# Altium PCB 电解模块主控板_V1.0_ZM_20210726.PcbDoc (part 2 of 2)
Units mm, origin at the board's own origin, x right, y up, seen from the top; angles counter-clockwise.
Board outline 150.25 x 100.26 mm, 2 copper layers (Top Layer, Bottom Layer); 209 components, 149 nets, 716 pads, 1259 vias.
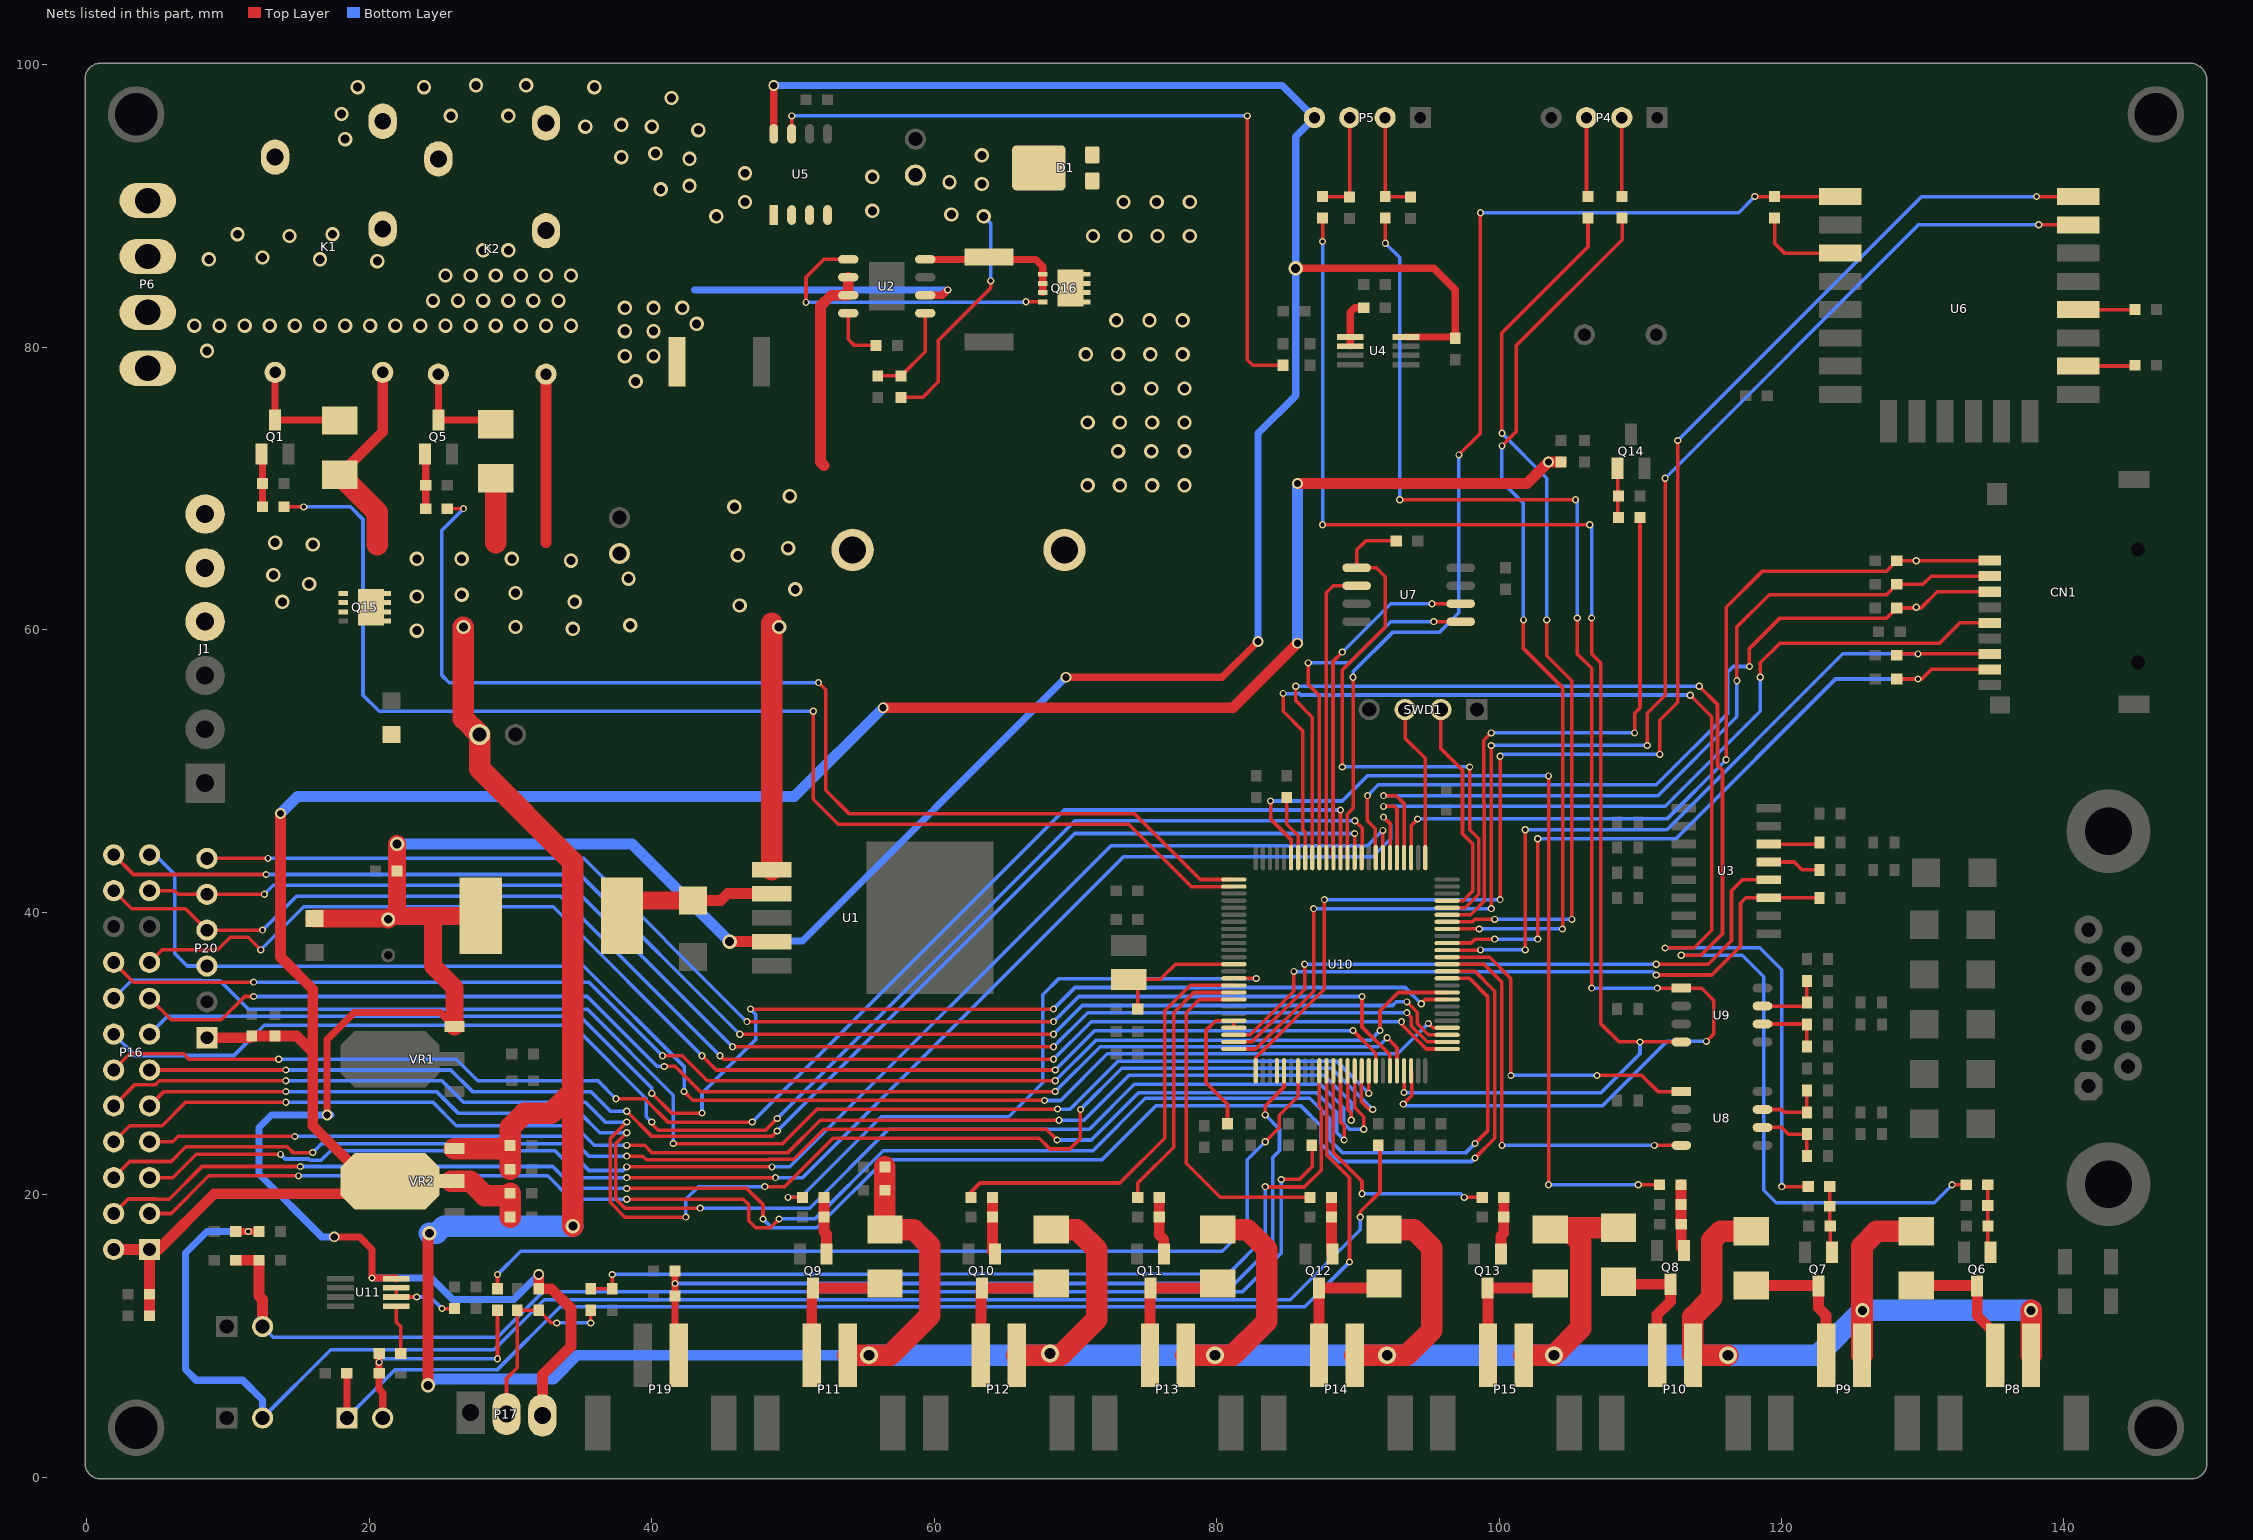
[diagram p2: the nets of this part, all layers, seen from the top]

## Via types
v1: diameter 1.016, hole 0.635, Top Layer to Bottom Layer, tented both sides, 1001 vias
v2: diameter 0.508, hole 0.305, Top Layer to Bottom Layer, tented both sides, 238 vias
v3: diameter 0.762, hole 0.508, Top Layer to Bottom Layer, tented both sides, 14 vias
v4: diameter 1.27, hole 0.762, Top Layer to Bottom Layer, tented both sides, 6 vias

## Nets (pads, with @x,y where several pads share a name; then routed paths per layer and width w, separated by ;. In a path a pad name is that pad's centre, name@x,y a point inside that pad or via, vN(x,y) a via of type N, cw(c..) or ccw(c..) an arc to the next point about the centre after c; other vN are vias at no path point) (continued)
NetC46_2: C46.2 P19.1 R48.1 U10.30 | length 63
  Top Layer w0.254: v2(83.439,25.654) 83.439,26.289 84.773,27.623 U10.30@84.773,28.772
  Top Layer w0.508: R48.1@41.656,14.605 v2(41.656,13.716) C46.2@41.656,12.827 41.656,10.16 41.91,9.906 P19.1@41.91,8.636
  Bottom Layer w0.254: v2(41.656,13.716) 81.28,13.716 83.972,16.408 83.972,22.631 84.455,23.114 84.455,24.638 v2(83.439,25.654)
NetC50_1: C50.1 U10.13 Y1.1 | length 10.2
  Top Layer w0.254: C50.1@74.422,33.147 74.422,34.614 Y1.1@73.787,35.249 76.016,35.249 77.089,36.322 U10.13@81.223,36.322
NetCN1_1: CN1.1 R63.2 U10.78 | length 57.3
  Top Layer w0.254: U10.78@93.773,43.872 93.773,46.148 v2(94.234,46.609) ; v2(116.078,50.8) 116.078,61.595 118.618,64.135 127.406,64.135 R63.2@128.168,64.897 v2(129.54,64.897) CN1.1@134.747,64.897
  Bottom Layer w0.254: v2(94.234,46.609) 111.887,46.609 v2(116.078,50.8)
NetCN1_2: CN1.2 R64.2 U10.79 | length 58.6
  Top Layer w0.254: v2(91.821,48.26) 92.71,48.26 93.273,47.697 U10.79@93.273,43.872 ; v2(116.84,56.388) 116.84,60.198 119.126,62.484 127.432,62.484 R64.2@128.168,63.221 130.023,63.221 130.599,63.797 CN1.2@134.747,63.797
  Bottom Layer w0.254: v2(91.821,48.26) 111.252,48.26 116.84,53.848 v2(116.84,56.388)
NetCN1_3: CN1.3 R65.2 U10.83 | length 57.1
  Top Layer w0.254: v2(90.678,48.26) 90.678,46.482 91.24,45.92 91.24,43.905 U10.83@91.273,43.872 ; v2(117.729,57.404) 117.729,58.674 119.888,60.833 127.457,60.833 R65.2@128.168,61.544 129.87,61.544 131.023,62.697 CN1.3@134.747,62.697
  Bottom Layer w0.254: v2(90.678,48.26) 91.44,49.022 111.125,49.022 116.205,54.102 116.205,57.023 116.586,57.404 v2(117.729,57.404)
  other v2: 129.54,61.595
NetCN1_5: CN1.5 U10.80 | length 54.8
  Top Layer w0.254: v2(91.821,47.498) 92.583,47.498 92.773,47.308 U10.80@92.773,43.872 ; v2(118.491,56.642) 118.491,57.658 119.888,59.055 131.191,59.055 132.633,60.497 CN1.5@134.747,60.497
  Bottom Layer w0.254: v2(91.821,47.498) 111.76,47.498 118.491,54.229 v2(118.491,56.642)
NetCN1_7: CN1.7 R66.2 U10.65 | length 53.7
  Top Layer w0.254: U10.65@96.323,37.322 98.695,37.322 v2(98.679,37.338) ; v2(101.854,37.338) v2(101.854,45.847) ; R66.2@128.168,58.191 128.274,58.297 v2(129.667,58.297) CN1.7@134.747,58.297
  Bottom Layer w0.254: v2(98.679,37.338) v2(101.854,37.338) ; v2(101.854,45.847) 111.887,45.847 124.337,58.297 v2(129.667,58.297)
NetCN1_8: CN1.8 R67.2 U10.66 | length 52.1
  Top Layer w0.254: U10.66@96.323,37.822 98.02,37.822 98.298,38.1 v2(99.695,38.1) ; v2(102.743,38.1) v2(102.743,45.212) ; R67.2@128.168,56.515 v2(129.667,56.515) 129.921,56.515 130.603,57.197 CN1.8@134.747,57.197
  Bottom Layer w0.254: v2(99.695,38.1) v2(102.743,38.1) ; v2(102.743,45.212) 112.522,45.212 123.825,56.515 v2(129.667,56.515)
NetD1_1: D1.1 L2.2 Q16.2
  other v1: 70.866,70.231 73.152,70.231 75.438,70.231 77.724,70.231 73.025,72.644 75.374,72.644 77.724,72.644 70.866,74.676 73.152,74.676 75.438,74.676 77.724,74.676 73.025,77.089 75.374,77.089 77.724,77.089 70.739,79.502 73.025,79.502 75.311,79.502 77.597,79.502 72.898,81.915 75.248,81.915 77.597,81.915 71.247,87.884 73.533,87.884 75.819,87.884 78.105,87.884 73.406,90.297 75.755,90.297 78.105,90.297
NetD3_2: D3.2 L1.1 U1.2 | length 11.3
  Top Layer w0.762: L1.1@37.893,39.751 L1.1@38.972,40.83 ; D3.2@42.926,40.83 44.894,40.83 45.388,41.324 U1.2@48.514,41.324
  Top Layer w1.27: L1.1@38.972,40.83 D3.2@42.926,40.83
NetD4_1: D4.1 K1.4 Q1.3 | length 8
  Top Layer w0.508: K1.4@13.335,78.232 Q1.3@13.335,74.86 17.86,74.86 D4.1@17.907,74.813
NetD5_1: D5.1 K2.4 Q5.3 | length 7.4
  Top Layer w0.508: K2.4@24.892,78.105 Q5.3@24.892,74.86 28.655,74.86 D5.1@28.956,74.559
NetD6_1: D6.1 P8.2 Q6.3 | length 9.8
  Top Layer w0.762: D6.1@129.54,13.579 133.811,13.579 Q6.3@133.858,13.532 133.858,11.43 135.128,10.16 P8.2@135.128,8.636
NetD7_1: D7.1 P9.2 Q7.3 | length 9.9
  Top Layer w0.762: D7.1@117.856,13.579 122.571,13.579 Q7.3@122.618,13.532 122.618,12.002 123.158,11.462 P9.2@123.158,8.636
NetD8_1: D8.1 P10.2 Q8.3 | length 9.2
  Top Layer w0.762: D8.1@108.458,13.833 108.632,13.659 Q8.3@112.141,13.659 112.141,12.446 111.188,11.493 P10.2@111.188,8.636
NetD9_1: D9.1 P11.2 Q9.3 | length 10
  Top Layer w0.762: P11.2@51.34,8.636 51.34,13.31 Q9.3@51.435,13.405 56.214,13.405 D9.1@56.515,13.706
NetD10_1: D10.1 P12.2 Q10.3 | length 9.8
  Top Layer w0.762: P12.2@63.309,8.636 63.309,13.341 Q10.3@63.373,13.405 67.993,13.405 D10.1@68.294,13.706
NetD11_1: D11.1 P13.2 Q11.3 | length 9.7
  Top Layer w0.762: P13.2@75.279,8.636 75.279,13.373 Q11.3@75.311,13.405 79.772,13.405 D11.1@80.073,13.706
NetD12_1: D12.1 P14.2 Q12.3 | length 9.5
  Top Layer w0.762: P14.2@87.249,8.636 Q12.3@87.249,13.405 91.552,13.405 D12.1@91.853,13.706
NetD13_1: D13.1 P15.2 Q13.3 | length 9.4
  Top Layer w0.762: P15.2@99.219,8.636 99.219,13.373 Q13.3@99.187,13.405 103.331,13.405 D13.1@103.632,13.706
NetJ1_4: J1.4 J1.5 J1.6 Q15.3
  other v1: 13.843,61.976 15.748,63.246 13.208,63.881 16.002,66.04 13.335,66.167
NetK1_1: K1.1 P6.3 P6.4
  other v1: 20.574,86.106 8.636,86.233 16.51,86.233 12.446,86.36 14.351,87.884 10.668,88.011 17.399,88.011
NetK2_1: K2.1 P6.1 P6.2
  other v1: 8.509,79.756 7.62,81.534 9.398,81.534 11.176,81.534 12.954,81.534 14.732,81.534 16.51,81.534 18.288,81.534 20.066,81.534 21.844,81.534 23.622,81.534 25.4,81.534 27.178,81.534 28.956,81.534 30.734,81.534 32.512,81.534 34.29,81.534 24.511,83.312 26.289,83.312 28.067,83.312 29.845,83.312 31.623,83.312 33.401,83.312 25.4,85.09 27.178,85.09 28.956,85.09 30.734,85.09 32.512,85.09 34.29,85.09 28.067,86.868 29.845,86.868
NetL3_2: L3.2 U10.21 U10.22 | length 10
  Top Layer w0.254: L3.2@80.772,25.019 80.772,26.416 79.248,27.94 79.248,31.623 79.947,32.322 U10.21@81.223,32.322 U10.22@81.223,31.822
NetP1_1: P1.1 TVS5.2 U10.36 | length 93
  Top Layer w0.254: U10.36@87.773,28.772 87.808,28.737 87.808,22.809 89.408,21.209 v2(89.408,15.24)
  Top Layer w0.508: P1.1@18.415,4.191 TVS5.2@18.415,7.366
  Bottom Layer w0.254: P1.1@18.415,4.191 21.844,7.62 29.083,7.62 33.528,12.065 86.233,12.065 v2(89.408,15.24)
NetP1_2: P1.2 R14.2 R16.1 TVS6.2 | length 16.6
  Top Layer w0.254: v2(29.083,8.382) R14.2@29.083,11.811
  Top Layer w0.508: R16.1@20.701,8.763 v2(20.701,8.128) TVS6.2@20.701,7.366 20.701,6.223 20.955,5.969 P1.2@20.955,4.191
  Bottom Layer w0.254: v2(20.701,8.128) 20.955,8.382 v2(29.083,8.382)
NetP2_2: P2.2 R5.2 R7.1 TVS1.2 | length 112.5
  Top Layer w0.254: 11.684,17.399 R5.2@12.192,17.399 ; v2(90.17,18.415) 90.17,18.796 91.567,20.193 91.567,23.368 R7.1@91.44,23.495
  Top Layer w0.508: TVS1.2@10.541,17.399 v2(11.43,17.399) 11.684,17.399
  Bottom Layer w0.254: P2.2@12.446,4.191 17.272,9.017 28.829,9.017 32.385,12.573 85.217,12.573 90.17,17.526 v2(90.17,18.415)
  Bottom Layer w0.508: v2(11.43,17.399) 8.509,17.399 6.985,15.875 6.985,7.62 7.747,6.858 11.049,6.858 12.446,5.461 P2.2@12.446,4.191
NetP3_2: P3.2 R6.2 R8.1 TVS2.2 | length 90.7
  Top Layer w0.254: v2(84.582,21.082) 85.852,21.082 86.766,21.996 86.766,23.47 R8.1@86.741,23.495
  Top Layer w0.762: TVS2.2@10.541,15.367 R6.2@12.192,15.367 12.192,12.827 12.446,12.573 P3.2@12.446,10.668
  Bottom Layer w0.254: P3.2@12.446,10.668 13.208,9.906 29.083,9.906 32.322,13.144 81.852,13.144 84.582,15.875 v2(84.582,21.082)
NetP4_2: P4.2 R11.1 | length 5.6
  Top Layer w0.254: P4.2@108.692,96.266 108.692,90.698 R11.1@108.712,90.678
NetP4_3: P4.3 R9.1 | length 5.6
  Top Layer w0.254: P4.3@106.192,96.266 106.192,90.785 R9.1@106.299,90.678
NetP5_2: P5.2 R12.1 TVS4.2 | length 7.4
  Top Layer w0.254: P5.2@91.928,96.266 91.928,90.698 R12.1@91.948,90.678 93.701,90.678 TVS4.2@93.726,90.653
NetP5_3: P5.3 R10.1 TVS3.2 | length 7.5
  Top Layer w0.254: R10.1@87.503,90.678 89.383,90.678 TVS3.2@89.408,90.653 89.428,90.673 P5.3@89.428,96.266
NetP16_3: P16.3 U10.61 | length 117.9
  Top Layer w0.254: P16.3@4.445,18.669 5.969,18.669 8.636,21.336 v2(14.986,21.336) ; v2(38.227,19.685) 46.482,19.685 46.863,19.304 46.863,18.161 47.371,17.653 48.387,17.653 v2(49.022,18.288) ; U10.61@96.323,35.322 97.901,35.322 99.187,34.036 99.187,24.511 v2(98.298,23.622)
  Bottom Layer w0.254: v2(14.986,21.336) 32.639,21.336 34.29,19.685 v2(38.227,19.685) ; v2(49.022,18.288) 51.562,18.288 56.388,23.114 71.247,23.114 74.955,26.822 86.589,26.822 88.011,25.4 88.011,23.876 88.9,22.987 97.663,22.987 v2(98.298,23.622)
NetP16_4: P16.4 U10.62 | length 122.6
  Top Layer w0.254: P16.4@1.905,18.669 2.934,19.698 4.871,19.698 4.885,19.685 5.842,19.685 8.153,21.996 v2(15.123,21.996) ; v2(38.227,20.447) 46.736,20.447 47.879,19.304 v2(47.879,18.288) ; U10.62@96.323,35.822 98.29,35.822 99.695,34.417 99.695,24.003 v2(98.298,22.606)
  Bottom Layer w0.254: v2(15.123,21.996) 32.995,21.996 34.544,20.447 v2(38.227,20.447) ; v2(47.879,18.288) 48.514,17.653 51.689,17.653 56.515,22.479 71.882,22.479 75.692,26.289 85.979,26.289 87.376,24.892 87.376,23.622 88.646,22.352 98.044,22.352 v2(98.298,22.606)
NetP16_5: P16.5 U10.81 | length 104.7
  Top Layer w0.254: P16.5@4.445,21.209 6.096,21.209 7.747,22.86 v2(13.716,22.86) ; v2(38.227,21.209) v2(48.768,21.209) ; v2(91.821,46.736) 92.306,46.251 92.306,43.905 U10.81@92.273,43.872
  Bottom Layer w0.254: v2(13.716,22.86) 14.046,22.53 15.705,22.53 15.781,22.454 16.612,22.454 17.272,23.114 33.147,23.114 35.052,21.209 v2(38.227,21.209) ; v2@48.641,21.209 v2(48.768,21.209) 50.673,21.209 73.406,43.942 91.059,43.942 92.329,45.212 92.329,46.228 v2(91.821,46.736)
NetP16_6: P16.6 U10.82 | length 103.8
  Top Layer w0.254: P16.6@1.905,21.209 3.048,22.352 5.969,22.352 7.01,23.393 14.199,23.393 14.605,22.987 v2(16.002,22.987) ; v2(38.227,21.971) v2(48.514,21.971) ; U10.82@91.773,43.872 v2(91.773,45.799)
  Bottom Layer w0.254: v2(16.002,22.987) 16.637,23.622 33.655,23.622 35.56,21.717 37.973,21.717 v2(38.227,21.971) ; v2@48.641,21.971 49.784,21.971 72.517,44.704 90.678,44.704 v2(91.773,45.799)
NetP16_7: P16.7 U10.38 | length 95.2
  Top Layer w0.254: P16.7@4.445,23.749 6.096,23.749 6.477,24.13 v2(14.732,24.13) ; v2(38.227,22.733) 39.37,22.733 39.624,22.479 48.268,22.479 48.293,22.504 50.063,22.504 52.197,24.638 67.945,24.638 v2(68.707,23.876) ; U10.38@88.773,28.772 88.773,25.146 89.027,24.892 v2(89.027,23.876)
  Bottom Layer w0.254: v2(14.732,24.13) 34.163,24.13 35.56,22.733 v2(38.227,22.733) ; v2(68.707,23.876) 71.12,23.876 74.473,27.229 87.071,27.229 88.519,25.781 88.519,24.384 v2(89.027,23.876)
NetP16_8: P16.8 U10.39 | length 98.2
  Top Layer w0.254: P16.8@1.905,23.749 3.048,24.892 5.334,24.892 6.985,26.543 v2(14.097,26.543) ; v2(38.227,23.495) 39.497,23.495 40.005,22.987 49.657,22.987 51.943,25.273 v2(68.834,25.273) ; U10.39@89.273,28.772 89.273,26.043 89.535,25.781 v2(89.535,25.273)
  Bottom Layer w0.254: v2(14.097,26.543) 24.511,26.543 26.162,24.892 34.544,24.892 35.941,23.495 v2(38.227,23.495) ; v2(68.834,25.273) 70.612,25.273 73.787,28.448 87.63,28.448 89.535,26.543 v2(89.535,25.273)
NetP16_9: P16.9 U10.40 | length 103.6
  Top Layer w0.254: P16.9@4.445,26.289 5.461,27.305 v2(14.097,27.305) ; v2(38.227,24.384) 37.465,23.622 37.465,19.693 38.108,19.05 v2(43.434,19.05) ; U10.40@89.773,28.772 89.773,26.178 90.424,25.527 v2(90.424,24.638)
  Bottom Layer w0.254: v2(14.097,27.305) 24.765,27.305 26.289,25.781 34.925,25.781 36.322,24.384 v2(38.227,24.384) ; v2(43.434,19.05) 51.181,19.05 56.769,24.638 70.993,24.638 74.168,27.813 87.351,27.813 89.002,26.162 89.002,25.052 89.416,24.638 v2(90.424,24.638)
NetP16_10: P16.10 U10.41 | length 110.3
  Top Layer w0.254: P16.10@1.905,26.289 3.416,27.8 4.871,27.8 5.139,28.067 v2(14.097,28.067) ; v2(38.227,25.146) 37.059,23.978 37.059,19.456 38.1,18.415 v2(42.418,18.415) ; v2(48.006,20.574) 49.403,20.574 52.832,24.003 67.437,24.003 68.199,23.241 69.596,23.241 70.358,24.003 v2(70.358,26.035) ; U10.41@90.273,28.772 90.24,28.739 90.24,26.6 90.805,26.035 v2(91.059,26.035)
  Bottom Layer w0.254: v2(14.097,28.067) 25.146,28.067 26.67,26.543 35.306,26.543 36.703,25.146 v2(38.227,25.146) ; v2(42.418,18.415) 42.418,19.685 43.307,20.574 v2(48.006,20.574) ; v2(70.358,26.035) 73.279,28.956 88.138,28.956 v2(91.059,26.035)
NetP16_11: P16.11 U10.86 | length 97.8
  Top Layer w0.254: P16.11@4.445,28.829 v2(14.097,28.829) ; v2(38.227,25.908) 39.98,24.155 48.539,24.155 v2(48.895,24.511) ; U10.86@89.773,43.872 v2(89.773,45.577)
  Bottom Layer w0.254: v2(14.097,28.829) 25.781,28.829 27.305,27.305 35.687,27.305 37.084,25.908 v2(38.227,25.908) ; v2(48.895,24.511) 69.961,45.577 v2(89.773,45.577)
NetP16_12: P16.12 U10.88 | length 101.9
  Top Layer w0.254: P16.12@1.905,28.829 3.048,29.972 6.858,29.972 7.239,29.591 v2(13.589,29.591) ; v2(37.465,26.797) 39.497,26.797 41.148,25.146 v2(47.117,25.146) ; U10.88@88.773,43.872 v2(88.773,47.244)
  Bottom Layer w0.254: v2(13.589,29.591) 26.162,29.591 27.686,28.067 36.195,28.067 v2(37.465,26.797) ; v2(47.117,25.146) 69.215,47.244 v2(88.773,47.244)
NetP16_13: P16.13 U10.58 | length 102.4
  Top Layer w0.254: v2(40.005,27.178) 41.402,25.781 v2(43.561,25.781) ; v2(46.99,33.147) v2(68.453,33.147) ; v2(94.488,33.528) 94.782,33.822 U10.58@96.323,33.822
  Bottom Layer w0.254: P16.13@4.445,31.369 5.702,32.626 13.322,32.626 13.335,32.639 34.925,32.639 40.005,27.559 v2(40.005,27.178) ; v2(43.561,25.781) 43.561,27.178 47.371,30.988 47.371,32.766 v2(46.99,33.147) ; v2(68.453,33.147) 69.977,34.671 93.345,34.671 v2(94.488,33.528)
NetP16_14: P16.14 U10.85 | length 105.2
  Top Layer w0.254: v2(40.005,25.146) 40.005,25.019 40.462,24.562 48.057,24.562 v2(48.895,25.4) ; v2(89.789,46.482) 90.306,45.965 90.306,43.905 U10.85@90.273,43.872
  Bottom Layer w0.254: P16.14@1.905,31.369 3.416,29.858 10.427,29.858 12.56,31.991 34.43,31.991 39.624,26.797 39.624,25.527 v2(40.005,25.146) ; v2(48.895,25.4) 69.977,46.482 v2(89.789,46.482)
NetP16_15: P16.15 U10.46 | length 95.9
  Top Layer w0.254: P16.15@4.445,33.909 5.969,32.385 9.525,32.385 11.176,34.036 v2(11.811,34.036) ; v2(40.894,29.083) 41.656,29.083 43.434,27.305 v2(68.58,27.305) ; v2(92.075,31.115) 92.773,30.417 U10.46@92.773,28.772
  Bottom Layer w0.254: v2(11.811,34.036) 35.433,34.036 40.386,29.083 v2(40.894,29.083) ; v2(68.58,27.305) 71.755,30.48 91.44,30.48 v2(92.075,31.115)
NetP16_16: P16.16 U10.42 | length 101.2
  Top Layer w0.254: v2(41.529,23.622) 49.276,23.622 51.721,26.067 v2(68.739,26.067) ; v2(90.773,27.178) U10.42@90.773,28.772
  Bottom Layer w0.254: P16.16@1.905,33.909 3.175,35.179 8.069,35.179 8.083,35.166 9.411,35.166 11.43,33.147 35.433,33.147 41.529,27.051 v2(41.529,23.622) ; v2(68.739,26.067) 69.628,26.067 73.025,29.464 88.487,29.464 v2(90.773,27.178)
NetP16_17: P16.17 U10.43 | length 97
  Top Layer w0.254: P16.17@4.445,36.449 5.334,37.338 9.271,37.338 10.16,38.227 11.43,38.227 v2(12.319,37.338) ; v2(43.561,29.845) 44.577,28.829 v2(68.58,28.829) ; v2(89.662,31.623) 91.273,30.012 U10.43@91.273,28.772
  Bottom Layer w0.254: v2(12.319,37.338) 15.367,40.386 33.02,40.386 v2(43.561,29.845) ; v2(68.58,28.829) 71.374,31.623 v2(89.662,31.623)
NetP16_18: P16.18 U10.59 | length 101.3
  Top Layer w0.254: P16.18@1.905,36.449 3.302,35.052 v2(11.811,35.052) ; v2(40.767,29.845) 42.164,29.845 43.942,28.067 v2(68.58,28.067) ; v2(91.567,31.623) 91.567,33.02 92.869,34.322 U10.59@96.323,34.322
  Bottom Layer w0.254: v2(11.811,35.052) 35.56,35.052 v2(40.767,29.845) ; v2(68.58,28.067) 71.438,30.924 90.868,30.924 v2(91.567,31.623)
NetP16_21: P16.21 P20.5 U10.52 | length 99.2
  Top Layer w0.254: P16.21@4.445,41.529 6.223,41.529 6.477,41.275 P20.5@8.509,41.275 v2(12.573,41.275) ; v2(45.72,30.48) v2(68.453,30.48) ; v2(93.472,32.893) 93.789,32.575 93.789,31.954 94.921,30.822 U10.52@96.323,30.822
  Bottom Layer w0.254: v2(12.573,41.275) 13.208,41.91 34.29,41.91 v2(45.72,30.48) ; v2(68.453,30.48) 70.866,32.893 v2(93.472,32.893)
NetP16_22: P16.22 P20.4 U10.51 | length 103.4
  Top Layer w0.254: P16.22@1.905,41.529 3.175,40.259 6.985,40.259 P20.4@8.509,38.735 v2(12.446,38.735) ; v2(44.831,29.845) 45.085,29.591 v2(68.453,29.591) ; v2(93.091,32.258) 93.091,32.078 94.847,30.322 U10.51@96.323,30.322
  Bottom Layer w0.254: v2(12.446,38.735) 14.859,41.148 33.528,41.148 v2(44.831,29.845) ; v2(68.453,29.591) 71.12,32.258 v2(93.091,32.258)
NetP16_23: P16.23 P20.3 U10.54 | length 105.8
  Top Layer w0.254: v2(42.291,27.305) 42.901,26.695 67.793,26.695 v2(67.818,26.67) ; v2(94.996,32.131) 95.305,31.822 U10.54@96.323,31.822
  Bottom Layer w0.254: P16.23@4.445,44.069 4.826,44.069 6.223,42.672 6.223,37.084 7.112,36.195 P20.3@8.509,36.195 8.509,36.178 35.196,36.178 42.291,29.083 v2(42.291,27.305) ; v2(67.818,26.67) 68.961,26.67 72.263,29.972 92.837,29.972 v2(94.996,32.131)
NetP16_24: P16.24 U10.53 | length 102.1
  Top Layer w0.254: P16.24@1.905,44.069 3.302,42.672 v2(12.7,42.672) ; v2(46.228,31.369) v2(68.453,31.369) ; v2(93.472,33.655) 94.196,32.931 94.196,32.122 94.996,31.322 U10.53@96.323,31.322
  Bottom Layer w0.254: v2(12.7,42.672) 34.925,42.672 v2(46.228,31.369) ; v2(68.453,31.369) 70.485,33.401 92.456,33.401 92.71,33.655 v2(93.472,33.655)
NetP17_2: P17.2 R19.1 R50.2 TVS11.2 | length 14.1
  Top Layer w0.254: P17.2@29.718,4.472 29.718,6.985 30.48,7.747 TVS11.2@30.48,11.811 R50.2@32.004,11.811 32.893,10.922 v2(33.274,10.922) ; v2(35.687,10.922) R19.1@35.687,11.811
  Bottom Layer w0.254: v2(33.274,10.922) v2(35.687,10.922)
NetP20_6: P20.6 U10.45 | length 93.4
  Top Layer w0.254: P20.6@8.509,43.815 v2(12.827,43.815) ; v2(46.736,32.258) v2(68.453,32.258) ; v2(90.297,34.036) 90.297,31.877 92.273,29.901 U10.45@92.273,28.772
  Bottom Layer w0.254: v2(12.827,43.815) 35.179,43.815 v2(46.736,32.258) ; v2(68.453,32.258) 70.231,34.036 v2(90.297,34.036)
NetQ1_1: Q1.1 R20.2 R21.2 | length 3.8
  Top Layer w0.508: Q1.1@12.385,72.46 12.446,72.399 R21.2@12.446,70.358 R20.2@12.446,68.707
NetQ5_1: Q5.1 R27.2 R28.2 | length 3.9
  Top Layer w0.508: Q5.1@23.942,72.46 24.003,72.399 R28.2@24.003,70.231 R27.2@24.003,68.58
NetQ6_1: Q6.1 R31.1 R34.1 TVS8.2 | length 4.9
  Top Layer w0.254: R31.1@134.595,20.701 R34.1@134.595,19.241 134.595,16.145 Q6.1@134.808,15.932
NetQ7_1: Q7.1 R32.1 R35.1 TVS9.2 | length 4.7
  Top Layer w0.254: R32.1@123.419,20.574 R35.1@123.419,19.177 123.419,17.805 TVS9.2@123.444,17.78 123.444,16.056 Q7.1@123.568,15.932
NetQ8_1: Q8.1 R33.1 R36.1 TVS10.2 | length 4.7
  Top Layer w0.762: R33.1@112.878,20.701 R36.1@112.878,19.304 112.878,17.932 TVS10.2@112.903,17.907 112.903,16.247 Q8.1@113.091,16.059
NetQ9_1: Q9.1 R37.1 R42.1 | length 4.1
  Top Layer w0.762: R37.1@52.197,19.812 R42.1@52.197,18.415 52.197,17.399 52.385,17.211 Q9.1@52.385,15.805
NetQ10_1: Q10.1 R38.1 R43.1 | length 4.1
  Top Layer w0.762: R38.1@64.135,19.812 R43.1@64.135,18.415 64.135,15.993 Q10.1@64.323,15.805
NetQ11_1: Q11.1 R39.1 R44.1 | length 4.1
  Top Layer w0.762: R39.1@75.946,19.812 R44.1@75.946,18.415 75.946,17.145 76.261,16.83 Q11.1@76.261,15.805
NetQ12_1: Q12.1 R40.1 R45.1 | length 4
  Top Layer w0.762: R40.1@88.138,19.812 R45.1@88.138,18.415 88.138,15.866 Q12.1@88.199,15.805
NetQ13_1: Q13.1 R41.1 R46.1 | length 4.1
  Top Layer w0.762: Q13.1@100.137,15.805 100.137,17.079 100.33,17.272 R46.1@100.33,18.415 R41.1@100.33,19.812
NetQ14_1: Q14.1 R57.2 R59.1 | length 3.5
  Top Layer w0.254: Q14.1@108.397,71.444 108.397,68.006 R57.2@108.458,67.945
NetQ16_1: Q16.1 U2.1 | length 22.1
  Top Layer w0.254: v2(50.927,83.185) 50.927,84.963 52.197,86.233 U2.1@53.917,86.233 ; v2(66.507,83.226) Q16.1@67.69,83.226
  Bottom Layer w0.254: v2(50.927,83.185) 66.466,83.185 v2(66.507,83.226)
NetQ16_3: Q16.3 R4.1 U2.8 | length 10.4
  Top Layer w0.508: U2.8@59.367,86.233 67.183,86.233 67.69,85.726 Q16.3@67.69,85.176 Q16.3@67.69,84.526 Q16.3@67.69,83.876
NetR2_2: R2.2 R13.1 U2.5 | length 6.8
  Top Layer w0.254: R13.1@56.007,77.978 R2.2@57.658,77.978 59.367,79.687 U2.5@59.367,82.423
NetR3_1: R3.1 U2.4 | length 4
  Top Layer w0.254: U2.4@53.917,82.423 53.917,80.576 54.356,80.137 R3.1@55.88,80.137
NetR9_2: R9.2 U10.69 | length 63.1
  Top Layer w0.254: U10.69@96.323,39.322 98.123,39.322 98.298,39.497 v2(99.695,39.497) ; v2(100.203,73.914) 100.203,81.026 106.299,87.122 R9.2@106.299,89.154 ; v2(103.378,60.706) 103.378,58.166 105.156,56.388 v2(105.156,39.497)
  Bottom Layer w0.254: v2(99.695,39.497) v2(105.156,39.497) ; v2(100.203,73.914) 103.378,70.739 v2(103.378,60.706)
NetR11_2: R11.2 U10.68 | length 63.8
  Top Layer w0.254: U10.68@96.323,38.822 v2(98.592,38.822) ; v2(100.203,73.025) 101.219,74.041 101.219,80.137 108.712,87.63 R11.2@108.712,89.154 ; v2(101.727,60.706) 101.727,58.674 104.521,55.88 104.521,38.862 v2(104.481,38.822)
  Bottom Layer w0.254: v2(98.592,38.822) v2(104.481,38.822) ; v2(100.203,73.025) 100.203,70.485 101.727,68.961 v2(101.727,60.706)
NetR14_1: R14.1 U10.32 | length 68
  Top Layer w0.254: R14.1@29.083,13.335 v2(29.083,14.351) ; v2(83.439,23.749) 84.43,24.74 84.43,25.629 85.773,26.972 U10.32@85.773,28.772
  Bottom Layer w0.254: v2(29.083,14.351) 30.734,16.002 80.391,16.002 82.169,17.78 82.169,22.479 v2(83.439,23.749)
NetR16_2: R16.2 U11.5 | length 3.5
  Top Layer w0.254: U11.5@21.914,12.106 21.914,10.979 22.225,10.668 R16.2@22.225,8.763
NetR18_2: R18.2 U11.6 U11.7 | length 5.1
  Top Layer w0.254: U11.7@21.914,13.406 U11.6@21.914,12.756 v2(23.368,12.756) ; v2(25.146,11.938) R18.2@26.035,11.938
  Bottom Layer w0.254: v2(23.368,12.756) 24.328,12.756 v2(25.146,11.938)
NetR19_2: R19.2 R22.2 U10.35 | length 64.8
  Top Layer w0.254: R19.2@35.687,13.335 R22.2@37.211,13.335 v2(37.211,14.351) ; v2(83.439,20.574) 83.464,20.549 86.208,20.549 87.401,21.742 87.401,26.137 87.273,26.265 U10.35@87.273,28.772
  Bottom Layer w0.254: v2(37.211,14.351) 80.835,14.414 83.439,17.018 v2@83.439,20.447
NetR20_1: R20.1 U10.2 | length 89.3
  Top Layer w0.254: R20.1@13.97,68.707 v2(15.367,68.707) ; v2(51.435,54.229) 51.435,48.006 53.213,46.228 73.787,46.228 78.193,41.822 U10.2@81.223,41.822
  Bottom Layer w0.254: v2(15.367,68.707) 18.669,68.707 19.558,67.818 19.558,55.372 20.701,54.229 v2(51.435,54.229)
NetR27_1: R27.1 U10.1 | length 79.8
  Top Layer w0.254: R27.1@25.527,68.58 v2(26.67,68.58) ; v2(51.816,56.261) 52.324,55.753 52.324,48.641 53.975,46.99 74.168,46.99 78.836,42.322 U10.1@81.223,42.322
  Bottom Layer w0.254: v2(26.67,68.58) 25.146,67.056 25.146,56.769 25.654,56.261 v2(51.816,56.261)
NetR29_2: R29.2 U4.1 U4.2 | length 3.5
  Top Layer w0.508: U4.2@89.465,80.091 U4.1@89.465,80.731 89.465,82.48 89.789,82.804 R29.2@90.424,82.804
NetR30_2: R30.2 U5.7 | length 53.5
  Top Layer w0.254: U5.7@49.911,95.123 v2(49.911,96.393) ; v2(82.169,96.393) 82.169,79.121 82.55,78.74 R30.2@84.709,78.74
  Bottom Layer w0.254: v2(49.911,96.393) v2(82.169,96.393)
NetR31_2: R31.2 U10.92 | length 99.8
  Top Layer w0.254: v2(85.598,56.007) 85.598,54.991 86.773,53.816 U10.92@86.773,43.872 ; v2(112.903,36.957) 114.3,36.957 115.824,38.481 115.824,50.063 115.468,50.419 115.468,54.712 v2(114.173,56.007) ; v2(132.08,20.701) R31.2@133.071,20.701
  Bottom Layer w0.254: v2(85.598,56.007) v2(114.173,56.007) ; v2(112.903,36.957) 117.221,36.957 118.745,35.433 118.745,20.32 119.634,19.431 130.81,19.431 v2(132.08,20.701)
NetR32_2: R32.2 U10.93 | length 88.4
  Top Layer w0.254: v2(84.709,55.499) 84.709,54.229 86.106,52.832 86.106,45.847 86.273,45.68 U10.93@86.273,43.872 ; v2(111.76,37.465) 111.785,37.49 113.817,37.49 115.062,38.735 115.062,53.848 v2(113.538,55.372) ; v2(120.015,20.574) R32.2@121.895,20.574
  Bottom Layer w0.254: v2(84.709,55.499) 84.734,55.474 85.819,55.474 85.844,55.499 85.958,55.385 113.525,55.385 v2(113.538,55.372) ; v2(111.76,37.465) 111.785,37.49 118.466,37.49 120.015,35.941 v2(120.015,20.574)
NetR33_2: R33.2 U10.95 | length 61.8
  Top Layer w0.254: v2(83.82,47.879) 83.82,46.609 85.273,45.156 U10.95@85.273,43.872 ; v2(103.505,20.701) v2(103.505,49.657) ; v2(109.855,20.701) R33.2@111.354,20.701
  Bottom Layer w0.254: v2(83.82,47.879) 88.9,47.879 90.678,49.657 v2(103.505,49.657) ; v2(103.505,20.701) v2(109.855,20.701)
NetR37_2: R37.2 U10.15 | length 45.8
  Top Layer w0.254: v2(49.657,19.812) R37.2@50.673,19.812 ; U10.15@81.223,35.322 v2@82.804,35.322
  Bottom Layer w0.254: v2(49.657,19.812) 50.546,19.812 56.261,25.527 65.278,25.527 67.691,27.94 67.691,34.163 68.834,35.306 v2(82.804,35.306)
NetR38_2: R38.2 U10.16 | length 30.3
  Top Layer w0.254: R38.2@62.611,19.812 62.611,20.193 63.246,20.828 73.152,20.828 76.327,24.003 76.327,33.02 78.129,34.822 U10.16@81.223,34.822
NetR39_2: R39.2 U10.17 | length 19
  Top Layer w0.254: R39.2@74.422,19.812 74.422,20.828 76.962,23.368 76.962,32.893 78.391,34.322 U10.17@81.223,34.322
NetR40_2: R40.2 U10.18 | length 24.2
  Top Layer w0.254: U10.18@81.223,33.822 78.78,33.822 77.851,32.893 77.851,22.225 80.264,19.812 R40.2@86.614,19.812
NetR41_2: R41.2 U10.37 | length 18.2
  Top Layer w0.254: U10.37@88.273,28.772 88.273,22.979 90.297,20.955 v2(90.297,20.066) ; v2(97.536,19.812) R41.2@98.806,19.812
  Bottom Layer w0.254: v2(90.297,20.066) 97.282,20.066 v2(97.536,19.812)
NetR47_1: R47.1 U3.14 | length 3.6
  Top Layer w0.254: U3.14@119.091,44.831 122.555,44.831 R47.1@122.682,44.958
NetR53_1: R53.1 U6.1 U10.87 | length 77.5
  Top Layer w0.254: U10.87@89.273,43.872 89.24,43.905 89.24,46.949 89.662,47.371 v2(89.662,56.642) ; v2(97.155,72.39) 98.679,73.914 v2(98.679,89.535) ; v2(118.11,90.678) R53.1@119.507,90.678 U6.1@124.155,90.678
  Bottom Layer w0.254: v2(89.662,56.642) 89.662,57.023 92.456,59.817 95.758,59.817 97.155,61.214 v2(97.155,72.39) ; v2(98.679,89.535) 116.967,89.535 v2(118.11,90.678)
NetR53_2: R53.2 U6.3 | length 6.7
  Top Layer w0.254: R53.2@119.507,89.154 119.507,87.376 120.205,86.678 U6.3@124.155,86.678
NetR54_2: R54.2 U6.18 | length 4
  Top Layer w0.254: U6.18@141.021,82.678 R54.2@145.034,82.677 R54.2@145.034,82.677
NetR55_1: R55.1 U6.16 | length 4
  Top Layer w0.254: U6.16@141.021,78.678 144.972,78.678 R55.1@145.034,78.74
NetR57_1: R57.1 U10.70 | length 40.7
  Top Layer w0.254: U10.70@96.323,39.822 97.988,39.822 98.958,40.792 98.958,47.752 98.908,47.803 98.908,52.172 v2(99.441,52.705) ; v2(109.601,52.705) 109.601,54.102 109.982,54.483 R57.1@109.982,67.945
  Bottom Layer w0.254: v2(99.441,52.705) v2(109.601,52.705)
NetR60_1: R60.1 U3.13 | length 3.8
  Top Layer w0.254: U3.13@119.091,43.561 120.904,43.561 121.454,43.011 R60.1@122.682,43.011
NetR61_1: R61.1 R69.1 U8.6 | length 4.9
  Top Layer w0.254: U8.6@118.653,24.765 120.015,24.765 120.495,24.285 R69.1@121.793,24.285 R61.1@121.793,22.733
NetR62_1: R62.1 R70.1 U8.7 | length 4.8
  Top Layer w0.254: U8.7@118.653,26.035 120.015,26.035 120.213,25.837 R62.1@121.793,25.837 R70.1@121.793,27.39
NetR68_2: R68.2 U7.1 U10.71 | length 42.3
  Top Layer w0.254: v2(88.9,50.292) 88.9,57.15 91.948,60.198 91.948,63.754 91.313,64.389 U7.1@89.916,64.389 89.916,65.659 90.551,66.294 R68.2@92.71,66.294 ; U10.71@96.323,40.322 97.599,40.322 98.552,41.275 98.552,45.212 97.917,45.847 v2(97.917,50.292)
  Bottom Layer w0.254: v2(88.9,50.292) v2(97.917,50.292)
NetR73_1: R73.1 R75.1 U9.6 | length 4.7
  Top Layer w0.254: U9.6@118.653,32.089 121.75,32.089 R75.1@121.793,32.046 R73.1@121.793,30.494
NetR74_1: R74.1 R76.1 U9.7 | length 4.8
  Top Layer w0.254: U9.7@118.653,33.359 121.553,33.359 R74.1@121.793,33.599 R76.1@121.793,35.151
NetR79_2: R79.2 U10.94 | length 4.6
  Top Layer w0.254: R79.2@84.963,48.133 84.963,46.228 85.773,45.418 U10.94@85.773,43.872
NetU6_21: U6.21 U10.25 | length 104.5
  Top Layer w0.254: U10.25@81.223,30.322 82.773,30.322 86.868,34.417 v2(86.868,40.259) ; v2(99.441,40.259) v2(99.441,51.816) ; v2(110.49,51.816) 110.49,54.102 111.76,55.372 v2(111.76,70.739) ; v2(138.208,88.678) U6.21@141.021,88.678
  Bottom Layer w0.254: v2(86.868,40.259) v2(99.441,40.259) ; v2(99.441,51.816) v2(110.49,51.816) ; v2(111.76,70.739) 129.699,88.678 v2(138.208,88.678)
NetU6_22: U6.22 U10.26 | length 106.4
  Top Layer w0.254: U10.26@82.773,28.772 82.773,29.704 83.427,30.358 83.444,30.358 87.63,34.544 v2(87.63,40.894) ; v2(100.076,40.894) v2(100.076,51.054) ; v2(111.379,51.181) 111.379,53.594 112.649,54.864 v2(112.649,73.406) ; v2(138.049,90.678) U6.22@141.021,90.678
  Bottom Layer w0.254: v2(87.63,40.894) v2(100.076,40.894) ; v2(100.076,51.054) 100.203,51.181 v2(111.379,51.181) ; v2(112.649,73.406) 129.921,90.678 v2(138.049,90.678)
NetU7_2: U7.2 U10.90 | length 21.1
  Top Layer w0.254: U10.90@87.773,43.872 87.773,62.627 88.265,63.119 U7.2@89.916,63.119
NetU7_5: U7.5 U10.91 | length 26.1
  Top Layer w0.254: v2(86.487,57.658) 86.487,56.134 87.273,55.348 U10.91@87.273,43.872 ; v2(95.377,60.579) U7.5@97.282,60.579
  Bottom Layer w0.254: v2(86.487,57.658) 89.408,57.658 92.329,60.579 v2(95.377,60.579)
NetU7_6: U7.6 U10.89 | length 24.6
  Top Layer w0.254: U10.89@88.273,43.872 88.24,43.905 88.24,57.76 v2(88.9,58.42) ; v2(95.25,61.849) U7.6@97.282,61.849
  Bottom Layer w0.254: v2(88.9,58.42) 92.329,61.849 v2(95.25,61.849)
NetU10_29: U10.29
RCS: K1.3 K2.3 R1.1 U2.6 | length 19.7
  Top Layer w0.508: U2.6@59.367,83.693 60.579,83.693 v2(60.96,84.074)
  Bottom Layer w0.508: 43.053,84.074 v2(60.96,84.074)
  other v1: 38.862,77.597 38.1,79.375 40.132,79.375 38.1,81.153 40.132,81.153 43.18,81.661 38.1,82.804 40.132,82.804 42.164,82.804
RXD1_485: U8.1 U10.64 | length 24.5
  Top Layer w0.254: U10.64@96.323,36.822 96.34,36.805 99.339,36.805 100.838,35.306 v2(100.838,28.448) ; v2(106.934,28.448) 110.109,28.448 111.252,27.305 U8.1@112.903,27.305
  Bottom Layer w0.254: v2(100.838,28.448) v2(106.934,28.448)
RXD2_485: R12.2 U9.1 U10.48 | length 106
  Top Layer w0.254: v2(91.948,87.376) R12.2@91.948,89.154 ; v2(92.964,69.215) v2(105.41,69.215) ; v2(93.218,26.416) 93.662,26.86 93.662,26.868 93.806,27.012 93.806,28.739 U10.48@93.773,28.772 ; v2(105.537,60.833) 105.537,58.293 106.553,57.277 v2(106.553,34.629) ; v2(111.21,34.629) U9.1@112.903,34.629 114.342,34.629 115.189,33.782 115.189,31.369 v2(114.681,30.861)
  Bottom Layer w0.254: v2(91.948,87.376) 92.964,86.36 v2(92.964,69.215) ; v2(93.218,26.416) 93.345,26.289 107.315,26.289 111.887,30.861 v2(114.681,30.861) ; v2(105.41,69.215) 105.537,69.088 v2(105.537,60.833) ; v2(106.553,34.629) v2(111.21,34.629)
RXD_233: U3.12 U10.24 | length 45.9
  Top Layer w0.254: U10.24@81.223,30.822 82.511,30.822 86.233,34.544 v2(86.233,36.322) ; v2(111.125,36.322) 114.808,36.322 116.459,37.973 116.459,41.529 117.221,42.291 U3.12@119.091,42.291
  Bottom Layer w0.254: v2(86.233,36.322) v2(111.125,36.322) v2@111.252,36.322
SWCLK: SWD1.3 U10.76 | length 11.1
  Top Layer w0.254: SWD1.3@93.345,54.356 93.345,52.324 94.773,50.896 U10.76@94.773,43.872
SWDIO: SWD1.2 U10.72 | length 15.9
  Top Layer w0.254: SWD1.2@95.885,54.356 95.885,51.57 97.409,50.046 97.409,45.568 98.146,44.831 98.146,41.504 97.464,40.822 U10.72@96.323,40.822
TXD1_485: U8.4 U10.63 | length 28.7
  Top Layer w0.254: U10.63@96.323,36.322 98.933,36.322 100.203,35.052 v2(100.203,23.495) ; v2(110.998,23.495) U8.4@112.903,23.495
  Bottom Layer w0.254: v2(100.203,23.495) v2(110.998,23.495)
TXD2_485: R10.2 U9.4 U10.47 | length 102.7
  Top Layer w0.254: v2(87.503,67.437) v2(106.426,67.437) ; v2(87.503,87.503) R10.2@87.503,89.154 ; v2(93.273,27.233) U10.47@93.273,28.772 ; v2(106.553,60.833) 106.553,58.293 107.188,57.658 107.188,32.131 108.5,30.819 v2(109.982,30.819) U9.4@112.903,30.819
  Bottom Layer w0.254: v2(87.503,67.437) v2(87.503,87.503) ; v2(93.273,27.233) 107.243,27.233 109.982,29.972 v2(109.982,30.819) ; v2(106.426,67.437) 106.553,67.31 v2(106.553,60.833)
TXD_232: R15.2 U3.11 U10.23 | length 48.3
  Top Layer w0.254: U10.23@81.223,31.322 82.376,31.322 85.471,34.417 v2(85.471,35.814) ; v2(111.125,35.56) 115.062,35.56 117.094,37.592 117.094,40.64 117.475,41.021 U3.11@119.091,41.021 R15.2@122.682,41.021
  Bottom Layer w0.254: v2(85.471,35.814) 85.496,35.789 110.896,35.789 v2(111.125,35.56)
V5.0: C14.2 C15.2 C16.2 C17.2 C19.2 C20.2 P16.1 P16.2 P20.1 R56.2 VR2.2 VR2.4 | length 178.4
  Top Layer w0.762: P16.2@1.905,16.129 P16.1@4.445,16.129 ; C15.2@4.445,11.43 C14.2@4.445,12.954 P16.1@4.445,16.129 ; P20.1@8.509,31.115 11.557,31.115 C17.2@11.684,31.242 C16.2@13.335,31.242 14.859,31.242 16.002,30.099 ; v3(13.716,46.99) 13.716,36.83 16.002,34.544 16.002,30.099 ; v3(56.388,54.483) 81.153,54.483 v3(85.725,59.055) ; v3(85.725,70.358) 101.981,70.358 v3(103.505,71.882) R56.2@104.394,71.882 ; P16.1@4.445,16.129 5.08,16.129 9.017,20.066 20.574,20.066 VR2.4@21.463,20.955 19.939,20.955 16.002,24.892 16.002,30.099
  Top Layer w1.524: VR2.2@25.808,20.969 27.164,20.969 28.194,19.939 29.803,19.939 C20.2@29.972,20.108 C19.2@29.972,18.415
  Bottom Layer w0.762: v3(13.716,46.99) 14.922,48.197 50.102,48.197 v3(56.388,54.483) ; v3(85.725,59.055) v3(85.725,70.358)
VDD5V: C2.1 C4.2 C13.2 C47.2 L1.2 P5.4 P17.3 R50.1 U1.4 U4.8 U5.8 U11.8 VR1.3 | length 265.3
  Top Layer w0.508: v3(17.018,25.654) 17.018,30.988 18.923,32.893 25.047,32.893 VR1.3@26.035,31.905 ; v3(17.526,17.018) 19.304,17.018 20.193,16.129 v2(20.193,14.097) 21.873,14.097 U11.8@21.914,14.056 ; U5.8@48.641,95.123 v3(48.641,98.552) ; v3(69.342,56.642) 80.391,56.642 v3(82.931,59.182) ; v1(85.598,85.598) 95.377,85.598 96.901,84.074 C47.2@96.901,80.645 96.815,80.731 U4.8@93.415,80.731
  Top Layer w0.762: v3(32.004,14.351) R50.1@32.004,13.335 32.893,13.335 34.29,11.938 34.29,9.271 32.258,7.239 P17.3@32.258,4.372 ; v1(45.515,37.924) U1.4@48.514,37.924
  Top Layer w1.27: C4.2@16.129,39.554 21.279,39.554 C2.1@21.336,39.497 C2.1@21.59,39.751 ; v1(21.971,44.831) C13.2@21.971,42.926 21.971,40.132 C2.1@21.59,39.751 ; VR1.3@26.035,31.905 26.035,34.671 24.511,36.195 24.511,39.751 ; L1.2@27.893,39.751 24.511,39.751 ; C2.1@21.59,39.751 24.511,39.751
  Bottom Layer w0.508: v3@17.272,25.654 v3(17.018,25.654) 13.081,25.654 12.192,24.765 12.192,21.463 16.637,17.018 v3(17.526,17.018) ; v2(20.193,14.097) 24.384,14.097 25.908,12.573 30.226,12.573 v3(32.004,14.351) ; v1(45.515,37.924) 45.564,37.973 50.673,37.973 v3(69.342,56.642) ; v3(48.641,98.552) 84.642,98.552 P5.4@86.928,96.266 85.598,94.936 v1(85.598,85.598) 85.598,76.581 82.931,73.914 v3(82.931,59.182)
  Bottom Layer w0.762: v1(21.971,44.831) 38.608,44.831 v1(45.515,37.924)
VDD12V: C1.1 C3.2 C8.2 C9.2 C11.1 C18.2 C21.2 D4.2 D5.2 D6.2 D7.2 D8.2 D9.2 D10.2 D11.2 D12.2 D13.2 K1.5 K2.5 L2.1 P8.1 P9.1 P10.1 P11.1 P12.1 P13.1 P14.1 P15.1 Q15.2 U1.1 U2.2 U2.3 VR2.3 | length 373.5
  Top Layer w0.762: D4.2@17.907,70.983 20.955,74.031 K1.5@20.955,78.232 ; v1(24.155,6.502) 24.155,17.17 v1(24.257,17.272) ; 32.512,66.167 K2.5@32.512,78.105 ; 52.197,71.628 51.943,71.882 51.943,82.931 52.705,83.693 U2.3@53.917,83.693 U2.2@53.917,84.963
  Top Layer w1.524: D4.2@17.907,70.983 20.574,68.316 20.574,66.04 ; VR2.3@26.035,23.269 29.746,23.269 C18.2@29.972,23.495 ; v1(26.67,60.198) 26.67,53.721 C1.1@27.813,52.578 27.813,50.165 34.417,43.561 34.417,27.305 ; 28.956,66.167 D5.2@28.956,70.729 ; C21.2@29.972,21.802 C18.2@29.972,23.495 ; v1(34.417,17.78) 34.417,27.305 ; U1.1@48.514,43.024 48.514,60.452 ; P11.1@53.88,8.636 v4(55.388,8.636) 56.896,8.636 59.69,11.43 59.69,16.383 58.537,17.536 D9.2@56.515,17.536 C9.2@56.515,20.32 C8.2@56.515,21.971 ; P12.1@65.849,8.636 68.961,8.636 71.501,11.176 71.501,16.129 70.094,17.536 D10.2@68.294,17.536 ; P13.1@77.819,8.636 81.153,8.636 83.566,11.049 83.566,16.129 82.159,17.536 D11.2@80.073,17.536 ; P14.1@89.789,8.636 93.472,8.636 95.25,10.414 95.25,16.256 93.97,17.536 D12.2@91.853,17.536 ; P15.1@101.759,8.636 v4(103.886,8.636) 105.796,10.546 105.796,16.632 104.892,17.536 D13.2@103.632,17.536 103.759,17.663 D8.2@108.458,17.663 ; v4(116.205,8.636) P10.1@113.728,8.636 113.728,11.367 115.062,12.7 115.062,16.764 115.707,17.409 D7.2@117.856,17.409 ; P9.1@125.698,8.636 125.698,16.351 126.756,17.409 D6.2@129.54,17.409 ; P8.1@137.668,8.636 v1(137.668,11.811) ; C18.2@29.972,23.495 29.972,24.765 30.988,25.781 32.893,25.781 34.417,27.305
  Bottom Layer w0.762: v1(24.155,6.502) 24.613,6.96 33.04,6.96 34.716,8.636 v4(55.388,8.636)
  Bottom Layer w1.524: v1(24.257,17.272) 24.765,17.272 25.273,17.78 v1(34.417,17.78) ; v4(55.388,8.636) v4(103.886,8.636) 122.555,8.636 v1(125.73,11.811) v1(137.668,11.811)
  other v1: 23.368,59.944 34.417,60.071 30.353,60.198 49.022,60.198 38.481,60.325 46.228,61.722 34.544,61.976 23.368,62.357 26.543,62.484 30.353,62.611 50.165,62.865 38.354,63.627 34.29,64.897 23.368,65.024 26.543,65.024 30.099,65.024 46.101,65.278 49.657,65.786 45.847,68.707 49.784,69.469
  other v4: 79.883,8.636 92.075,8.636 68.199,8.763
VDD_ELE: C7.1 D1.2 R2.1 U5.3 U5.4 | length 16.6
  Top Layer w0.254: R2.1@57.658,76.454 59.182,76.454 60.3,77.572 60.3,80.493 64.008,84.201 v2(64.008,84.709)
  Bottom Layer w0.254: v1(63.5,89.281) 64.008,88.773 v2(64.008,84.709)
  other v1: 61.214,89.408 55.626,89.662 63.373,91.567 61.087,91.694 55.626,92.075 63.373,93.599
VO+: K1.2 K2.2 U5.1 U5.2
  other v1: 44.577,89.281 46.609,90.297 40.64,91.186 42.672,91.44 46.609,92.329 42.672,93.345 37.846,93.472 40.259,93.726 18.288,94.742 43.307,95.377 35.306,95.631 40.005,95.631 37.846,95.758 25.781,96.393 29.845,96.393 18.034,96.52 41.402,97.663 19.177,98.425 23.876,98.425 35.941,98.425 27.559,98.552 31.115,98.552
pads on no net: CN1.0 CN1.9 J2.1 J2.6 U3.7 U3.9 U4.5 U4.6 U4.7 U6.2 U6.4 U6.5 U6.6 U6.7 U6.9 U6.10 U6.11 U6.12 U6.13 U6.14 U6.17 U6.19 U6.20 U10.3 U10.4 U10.5 U10.7 U10.8 U10.9 U10.55 U10.60 U10.67 U10.77 U10.84 U10.96 U10.97 U10.98 U11.1 U11.2 U11.3

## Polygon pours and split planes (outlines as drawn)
RCS on Bottom Layer "Top Layer-No Net" (solid, remove dead copper, pour order 0): 11.049,98.806 14.732,98.806 16.002,98.806 16.256,98.552 16.383,98.425 25.908,98.425 27.432,98.425 27.813,98.044 31.496,94.361 37.084,94.361 38.1,94.361 42.672,89.789 44.069,88.392 44.069,77.724 44.069,77.343 43.307,76.581 43.18,76.454 40.259,76.454 38.862,76.454 38.1,77.216 37.084,78.232 37.084,80.391 37.084,86.487 35.179,88.392 34.163,89.408 30.48,89.408 11.303,89.408 10.795,89.916 10.16,90.551 10.16,94.488 10.16,97.917 11.049,98.806
NetC32_2 on Bottom Layer "Top Layer-No Net" (solid, remove dead copper, pour order 6): 141.478,16.637 141.478,10.414 141.478,8.89 144.145,8.89 144.145,-1.524 144.018,-1.651 152.019,-1.651 152.019,48.641 152.273,48.895 151.257,49.911 143.129,49.911 140.208,49.911 139.192,48.895 139.192,44.45 139.192,42.799 140.081,41.91 140.335,41.656 143.256,41.656 145.542,41.656 146.05,41.148 146.304,40.894 146.304,37.719 146.304,25.273 146.05,25.019 145.542,24.511 144.653,24.511 140.462,24.511 139.7,23.749 139.192,23.241 139.192,20.828 139.192,18.669 139.827,18.034 141.224,16.637 141.351,16.637
GND on Bottom Layer "Top Layer-No Net" (solid, remove dead copper, pour order 12): -5.08,104.648 153.162,104.648 154.051,105.537 155.956,103.632 155.956,-2.921 119.634,-2.921 116.205,-6.35 112.395,-2.54 -6.096,-2.54 -6.096,105.537 -5.842,105.791
NetC32_2 on Top Layer "Top Layer-No Net" (solid, remove dead copper, pour order 8): 142.24,16.637 142.24,8.89 144.145,8.89 144.145,-1.524 144.018,-1.651 152.019,-1.651 152.019,48.641 152.273,48.895 151.257,49.911 143.129,49.911 140.208,49.911 139.192,48.895 139.192,44.45 139.192,42.799 140.081,41.91 140.335,41.656 143.256,41.656 145.542,41.656 146.05,41.148 146.304,40.894 146.304,37.719 146.304,25.273 146.05,25.019 145.542,24.511 144.653,24.511 140.462,24.511 139.7,23.749 139.192,23.241 139.192,20.828 139.192,18.669 139.827,18.034 141.224,16.637 141.351,16.637
GND on Top Layer "Top Layer-No Net" (solid, remove dead copper, pour order 10): -19.431,108.204 -11.92,100.693 156.464,100.693 156.464,-1.651 -7.747,-1.651 -7.747,100.693

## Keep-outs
Keep-Out Layer:
  lines w0.254: 0.746,100 148.746,100 ; 1,100 ccw(c1,99) 0,99 0,1 ccw(c1,1) 1,0 149,0 ccw(c149,1) 150,1 150,99 ccw(c148.859,98.859) 148.717,100
Mechanical 1:
  lines w0.254: 0.762,100 148.762,100 ; 1.016,100 ccw(c1.016,99) 0.016,99 0.016,1 ccw(c1.016,1) 1.016,0 149.016,0 ccw(c149.016,1) 150.016,1 150.016,99 ccw(c148.875,98.859) 148.733,100

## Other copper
Top Layer:
  rectangle net GND: 6.096,56.388 10.795,57.277
  rectangle net GND: 5.969,48.641 11.43,49.911
  rectangle net GND: 5.588,52.705 11.176,53.594
  rectangle net GND: 55.753,81.534 57.531,87.122
  rectangle net GND: 52.578,36.703 66.675,42.799
  rectangle net GND: 57.785,33.909 61.976,45.466
  region net VDD12V: 24.511,53.34 25.273,54.102 25.273,60.452 25.654,60.833 27.813,60.833 29.083,59.563 29.083,51.943 28.321,51.181 20.447,51.181 20.193,51.435 20.193,52.959 20.574,53.34
  region net RCS: 37.211,83.566 43.434,83.566 43.942,83.058 43.942,77.216 43.307,76.581 38.608,76.581 37.211,77.978
  region net NetK2_1: 1.524,83.82 22.987,83.82 29.337,90.17 33.782,90.17 35.56,88.392 35.56,81.788 33.274,79.502 10.287,79.502 7.747,76.962 0.762,76.962 0.508,77.216 0.508,82.804
  region net NetK1_1: 1.27,91.694 9.271,91.694 22.225,91.694 23.241,90.678 23.241,85.471 22.352,84.582 1.27,84.582 0.762,85.09 0.762,91.186
  region net VO+: 17.145,99.314 41.402,99.314 47.625,93.091 49.911,93.091 50.419,92.583 50.419,88.519 50.165,88.265 37.211,88.265 30.607,94.869 22.606,94.869 21.251,93.514 17.145,93.514 17.145,94.028 17.145,94.869
  region net VDD_ELE: 68.961,94.996 69.469,94.488 69.469,89.662 68.072,88.265 50.673,88.265 50.673,93.091 60.071,93.091 61.976,94.996
  region net NetD1_1: 77.851,59.69 79.248,61.087 79.248,93.091 77.47,94.869 69.85,94.869 69.85,86.868 68.603,85.503 68.603,75.819 65.532,72.074 65.532,59.69
  region net VDD12V: 19.177,58.928 53.467,58.928 57.023,62.484 57.023,71.374 56.007,72.39 44.196,72.39 38.354,66.548 19.177,66.548
  region net NetJ1_4: 5.08,70.104 9.271,70.104 11.938,67.437 18.034,67.437 18.796,66.675 18.796,61.214 18.669,61.087 12.573,61.087 10.287,58.801 5.334,58.801 4.572,59.563 4.572,69.596
Bottom Layer:
  rectangle net RCS: 12.827,91.694 13.843,95.631
  rectangle net RCS: 11.684,93.218 15.113,93.98
  rectangle net RCS: 24.511,90.932 25.273,93.472
  rectangle net RCS: 23.114,92.837 27.178,93.726
  region net NetK2_1: 1.651,83.82 22.987,83.82 27.305,88.138 34.163,88.138 35.433,86.868 35.433,81.915 33.147,79.629 9.779,79.629 7.239,77.089 0.889,77.089 0.635,77.343 0.635,82.804
  region net NetK1_1: 6.35,91.694 9.271,88.773 22.606,88.773 23.114,88.265 23.114,85.344 22.352,84.582 1.143,84.582 0.508,85.217 0.508,91.059 1.143,91.694
  region net VO+: 17.145,99.314 41.402,99.314 47.625,93.091 49.911,93.091 50.419,92.583 50.419,88.519 50.165,88.265 43.18,88.265 30.734,94.869 22.606,94.869 21.765,94.028 17.145,94.028 17.145,94.869
  region net NetJ1_4: 5.08,70.104 9.271,70.104 11.938,67.437 18.034,67.437 18.796,66.675 18.796,61.214 18.669,61.087 12.573,61.087 10.287,58.801 5.334,58.801 4.572,59.563 4.572,69.596

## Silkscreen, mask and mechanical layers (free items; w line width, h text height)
Top Overlay:
  circle w0.5: c3.5,3.5 r2.5
  circle w0.5: c3.5,96.5 r2.5
  circle w0.5: c146.5,96.5 r2.5
  circle w0.5: c146.5,3.5 r2.5
  text "uart3" at 79.248,95.631 h2.03
  text "uart1" at 115.062,94.234 h2.03
  text "电解" at 7.366,93.472 h2.03
  text "+" at 9.906,89.408 h2.03
  text "+" at 9.906,85.852 h2.03
  text "-" at 10.287,82.169 h2.03 r90
  text "-" at 10.16,79.375 h2.03 r90
  text "+" at 10.668,67.564 h2.03
  text "+" at 10.541,64.135 h2.03
  text "+" at 10.795,60.198 h2.03
  text "-" at 11.684,56.515 h2.03 r90
  text "-" at 11.557,52.832 h2.03 r90
  text "AOPWMG_V1.0 20210728" at 49.276,50.927 h2.03
  text "-" at 11.557,49.276 h2.03 r90
Bottom Overlay:
  text "水位L" at 13.335,8.255 h2.03
  text "电磁阀1" at 54.991,3.302 h2.03
  text "电磁阀3" at 79.502,3.175 h2.03
  text "电磁阀4" at 91.44,3.175 h2.03
  text "泵2" at 125.603,3.175 h2.03
  text "压力阀" at 43.18,3.048 h2.03
  text "电磁阀2" at 67.818,3.048 h2.03
  text "电磁阀5" at 103.378,3.048 h2.03
  text "泵1" at 113.665,3.048 h2.03
  text "泵3" at 137.795,3.048 h2.03
  text "TDS" at 21.336,1.778 h2.03
  text "水位H" at 13.589,1.524 h2.03
  text "流量" at 31.496,1.143 h2.03
Bottom Solder:
  region: 6.35,91.694 9.271,88.773 22.606,88.773 22.606,85.471 22.098,84.963 0.762,84.963 0.762,91.313 1.143,91.694
  region: 1.27,83.185 23.368,83.185 29.718,89.535 33.782,89.535 35.052,88.265 35.052,82.296 32.512,79.756 9.779,79.756 7.239,77.216 0.762,77.216 0.762,82.677
  region: 17.145,99.314 41.402,99.314 47.625,93.091 49.911,93.091 50.419,92.583 50.419,88.519 50.165,88.265 43.18,88.265 29.777,95.377 22.352,95.377 21.003,94.028 17.145,94.028 17.145,94.869
  region: 25.908,59.436 52.959,59.436 56.388,62.865 56.388,71.247 55.753,71.882 45.847,71.882 39.751,65.786 25.908,65.786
